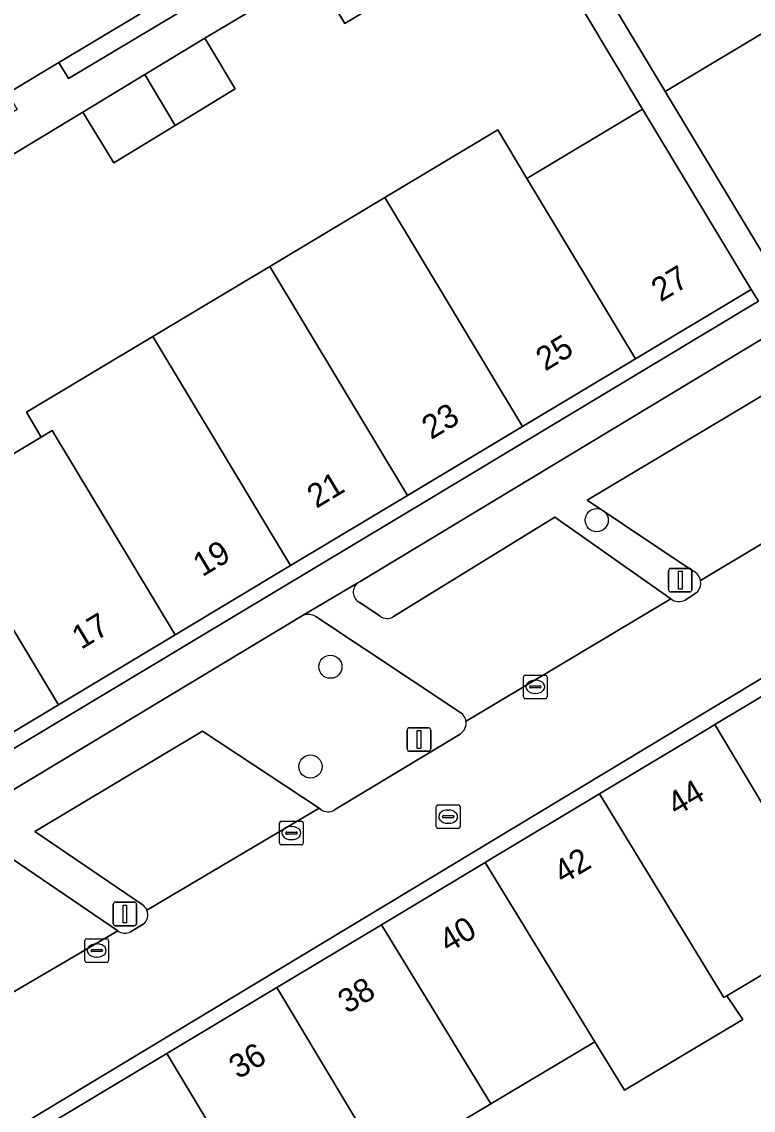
# Model space of a CAD drawing. Extents: x 161771 to 163125, y 382475 to 383179.
# Drawn here: x 162265.66 to 162296.6, y 382884.75 to 382930.82 of the extents above; entities that cross this region are included whole.
import ezdxf

# ---------------------------------------------------------------- set-up
doc = ezdxf.new("R2010")
doc.units = 0
for name, color, linetype in [('IMGEO_Boom', 7, 'Continuous'), ('IMGEO_Erf', 7, 'Continuous'), ('IMGEO_Groenvoorziening', 7, 'Continuous'), ('IMGEO_Kolk', 7, 'Continuous'), ('IMGEO_Lichtmast', 7, 'Continuous'), ('IMGEO_Pand', 7, 'Continuous'), ('IMGEO_Pand_nummerreeks', 7, 'Continuous'), ('IMGEO_Parkeervlak_open', 7, 'Continuous'), ('IMGEO_Rioolput', 7, 'Continuous'), ('IMGEO_Voetpad_open', 7, 'Continuous'), ('IMGEO_Woonerf_open', 7, 'Continuous')]:
    doc.layers.add(name, color=color, linetype=linetype)

msp = doc.modelspace()

# ---------------------------------------------------------------- linework, layer by layer
at = {"layer": 'IMGEO_Boom'}
for centre in [(162289.978, 382909.728), (162278.713, 382903.523), (162277.873, 382899.3)]:
    msp.add_circle(centre, 0.489, dxfattribs=at)
at = {"layer": 'IMGEO_Erf'}
for points in [[(162262.013, 382910.567), (162266.485, 382913.246), (162265.858, 382914.293), (162271.211, 382917.503), (162276.152, 382920.466), (162281.023, 382923.387), (162285.792, 382926.247), (162287.024, 382924.194), (162291.914, 382927.129), (162285.715, 382937.507)], [(162281.803, 382932.258), (162279.323, 382930.753), (162278.026, 382932.89), (162273.401, 382930.122), (162274.693, 382927.982), (162272.15, 382926.433), (162269.55, 382924.849), (162268.251, 382927.002), (162263.671, 382924.234)], [(162303.877, 382907.217), (162266.56, 382884.689), (162262.058, 382881.971), (162248.32, 382873.678), (162240.406, 382868.9), (162233.779, 382879.947)], [(162236.885, 382871.083), (162239.66, 382866.479), (162244.449, 382869.355), (162248.972, 382872.07), (162251.245, 382873.435), (162253.519, 382874.8), (162253.925, 382875.044), (162253.312, 382876.074), (162257.837, 382878.767), (162262.352, 382881.479), (162266.86, 382884.187), (162271.804, 382887.157), (162276.448, 382889.947), (162280.878, 382892.607), (162285.267, 382895.243), (162285.489, 382895.377), (162290.1, 382898.147), (162294.711, 382900.917), (162294.978, 382901.077), (162299.213, 382903.621)], [(162300.168, 382892.396), (162295.482, 382889.595), (162296.156, 382888.587), (162291.149, 382885.601), (162289.899, 382887.65), (162285.499, 382885.022), (162281.001, 382882.337), (162281.673, 382881.295), (162276.987, 382878.494), (162277.661, 382877.486), (162272.654, 382874.5), (162271.398, 382876.603), (162266.883, 382873.907), (162262.361, 382871.206), (162257.821, 382868.496), (162259.108, 382866.333), (162254.113, 382863.36), (162253.512, 382864.374), (162249.033, 382861.693), (162244.335, 382858.88), (162238.836, 382855.588)]]:
    msp.add_lwpolyline(points, dxfattribs=at)
msp.add_lwpolyline([(162296.82, 382918.994), (162296.509, 382919.492), (162291.612, 382916.553), (162286.844, 382913.691), (162281.974, 382910.768), (162277.034, 382907.803), (162272.149, 382904.871), (162267.212, 382901.908), (162261.895, 382898.717), (162262.21, 382898.195), (162282.281, 382910.257)], close=True, dxfattribs=at)
at = {"layer": 'IMGEO_Groenvoorziening'}
msp.add_lwpolyline([(162273.693, 382932.984), (162267.225, 382929.098), (162267.646, 382928.417), (162274.104, 382932.301)], close=True, dxfattribs=at)
for points in [[(162297.006, 382917.412), (162279.978, 382907.135), (162279.87, 382907.071)], [(162289.571, 382910.581), (162298.495, 382915.904)], [(162294.061, 382907.566), (162289.571, 382910.581)], [(162281.384, 382905.65), (162288.207, 382909.855), (162293.118, 382906.394)], [(162293.716, 382906.349), (162294.179, 382906.647)], [(162279.937, 382906.257), (162280.807, 382905.673)], [(162277.57, 382905.706), (162263.657, 382897.322), (162263.621, 382897.301)], [(162284.232, 382901.576), (162278.098, 382905.651)], [(162270.759, 382893.457), (162266.22, 382896.553), (162273.303, 382900.803), (162278.236, 382897.536), (162278.293, 382897.498)], [(162278.89, 382897.465), (162284.198, 382900.673)], [(162263.657, 382896.487), (162269.722, 382892.346)], [(162270.268, 382892.306), (162270.8, 382892.625)]]:
    msp.add_lwpolyline(points, dxfattribs=at)
for centre, radius, start, end in [((162293.836, 382907.072), 0.543, 10.3968, 65.5333), ((162280.171, 382906.686), 0.489, 128.052, 241.3588), ((162293.837, 382907.068), 0.542, 309.0544, 10.8212), ((162293.455, 382906.872), 0.585, 234.8516, 296.5415), ((162277.776, 382905.122), 0.619, 58.6595, 109.4468), ((162281.111, 382906.05), 0.484, 231.0902, 304.3444), ((162283.908, 382901.133), 0.549, 9.2422, 53.8647), ((162283.91, 382901.137), 0.546, 301.7922, 8.8167), ((162278.614, 382897.895), 0.511, 231.0026, 302.6696), ((162270.473, 382893.025), 0.518, 21.8831, 56.5389), ((162270.472, 382893.027), 0.519, 309.2397, 21.6444), ((162270.028, 382892.771), 0.524, 234.2974, 297.3226)]:
    msp.add_arc(centre, radius, start, end, dxfattribs=at)
at = {"layer": 'IMGEO_Kolk'}
for p, q in [((162286.881, 382902.247), (162286.881, 382903.099)), ((162286.956, 382903.173), (162287.808, 382903.173)), ((162287.369, 382902.953), (162287.394, 382902.953)), ((162287.882, 382903.099), (162287.882, 382902.247)), ((162287.14, 382902.667), (162287.14, 382902.679)), ((162287.578, 382902.63), (162287.18, 382902.63)), ((162287.183, 382902.716), (162287.581, 382902.716)), ((162287.392, 382902.393), (162287.367, 382902.393)), ((162287.624, 382902.679), (162287.624, 382902.667)), ((162287.808, 382902.173), (162286.956, 382902.173)), ((162276.565, 382896.059), (162276.565, 382896.911)), ((162276.64, 382896.985), (162277.492, 382896.985)), ((162277.053, 382896.765), (162277.078, 382896.765)), ((162277.566, 382896.911), (162277.566, 382896.059)), ((162276.824, 382896.479), (162276.824, 382896.491)), ((162277.262, 382896.442), (162276.864, 382896.442)), ((162276.867, 382896.528), (162277.265, 382896.528)), ((162277.308, 382896.491), (162277.308, 382896.479)), ((162277.492, 382895.985), (162276.64, 382895.985)), ((162277.076, 382896.205), (162277.051, 382896.205)), ((162268.335, 382891.087), (162268.335, 382891.939)), ((162268.41, 382892.013), (162269.262, 382892.013)), ((162268.823, 382891.793), (162268.848, 382891.793)), ((162269.336, 382891.939), (162269.336, 382891.087)), ((162268.594, 382891.507), (162268.594, 382891.519)), ((162269.032, 382891.47), (162268.634, 382891.47)), ((162268.637, 382891.556), (162269.035, 382891.556)), ((162268.846, 382891.233), (162268.821, 382891.233)), ((162269.078, 382891.519), (162269.078, 382891.507)), ((162269.262, 382891.013), (162268.41, 382891.013))]:
    msp.add_line(p, q, dxfattribs=at)
for points in [[(162286.881, 382902.247), (162286.881, 382903.099)], [(162286.956, 382903.173), (162287.808, 382903.173)], [(162287.882, 382903.099), (162287.882, 382902.247)], [(162287.808, 382902.173), (162286.956, 382902.173)], [(162276.565, 382896.059), (162276.565, 382896.911)], [(162276.64, 382896.985), (162277.492, 382896.985)], [(162277.566, 382896.911), (162277.566, 382896.059)], [(162277.492, 382895.985), (162276.64, 382895.985)], [(162268.335, 382891.087), (162268.335, 382891.939)], [(162268.41, 382892.013), (162269.262, 382892.013)], [(162269.336, 382891.939), (162269.336, 382891.087)], [(162269.262, 382891.013), (162268.41, 382891.013)]]:
    msp.add_lwpolyline(points, dxfattribs=at)
for centre, radius, start, end in [((162286.958, 382903.097), 0.0765, 91.552, 178.448), ((162286.958, 382903.097), 0.0765, 91.552, 178.448), ((162287.806, 382903.097), 0.0765, 1.552, 88.448), ((162287.806, 382903.097), 0.0765, 1.552, 88.448), ((162287.18, 382902.676), 0.0403, 85.8775, 175.7526), ((162287.177, 382902.666), 0.0366, 178.938, 274.7102), ((162287.581, 382902.673), 0.043, 264.8664, 352.4533), ((162287.585, 382902.678), 0.0386, 1.7309, 96.639), ((162286.958, 382902.249), 0.0765, 181.552, 268.448), ((162286.958, 382902.249), 0.0765, 181.552, 268.448), ((162287.806, 382902.249), 0.0765, 271.552, 358.448), ((162287.806, 382902.249), 0.0765, 271.552, 358.448), ((162276.642, 382896.909), 0.0765, 91.552, 178.448), ((162276.642, 382896.909), 0.0765, 91.552, 178.448), ((162277.49, 382896.909), 0.0765, 1.552, 88.448), ((162277.49, 382896.909), 0.0765, 1.552, 88.448), ((162276.864, 382896.488), 0.0403, 85.8775, 175.7526), ((162276.861, 382896.478), 0.0366, 178.938, 274.7102), ((162277.265, 382896.485), 0.043, 264.8664, 352.4533), ((162277.269, 382896.49), 0.0386, 1.7309, 96.639), ((162276.642, 382896.061), 0.0765, 181.552, 268.448), ((162276.642, 382896.061), 0.0765, 181.552, 268.448), ((162277.49, 382896.061), 0.0765, 271.552, 358.448), ((162277.49, 382896.061), 0.0765, 271.552, 358.448), ((162268.412, 382891.937), 0.0765, 91.552, 178.448), ((162268.412, 382891.937), 0.0765, 91.552, 178.448), ((162269.26, 382891.937), 0.0765, 1.552, 88.448), ((162269.26, 382891.937), 0.0765, 1.552, 88.448), ((162268.634, 382891.516), 0.0403, 85.8775, 175.7526), ((162268.631, 382891.506), 0.0366, 178.938, 274.7102), ((162269.035, 382891.513), 0.043, 264.8664, 352.4533), ((162269.039, 382891.518), 0.0386, 1.7309, 96.639), ((162268.412, 382891.089), 0.0765, 181.552, 268.448), ((162268.412, 382891.089), 0.0765, 181.552, 268.448), ((162269.26, 382891.089), 0.0765, 271.552, 358.448), ((162269.26, 382891.089), 0.0765, 271.552, 358.448)]:
    msp.add_arc(centre, radius, start, end, dxfattribs=at)
for centre, major_axis, ratio, start_param, end_param in [((162287.368, 382902.673), (-0.387, 0.002), 0.722429, 4.712389, 7.853982), ((162287.393, 382902.673), (-0.39, 0.002), 0.717154, 1.570796, 4.712389), ((162277.052, 382896.485), (-0.387, 0.002), 0.722429, 4.712389, 7.853982), ((162277.077, 382896.485), (-0.39, 0.002), 0.717154, 1.570796, 4.712389), ((162268.822, 382891.513), (-0.387, 0.002), 0.722429, 4.712389, 7.853982), ((162268.847, 382891.513), (-0.39, 0.002), 0.717154, 1.570796, 4.712389)]:
    msp.add_ellipse(centre, major_axis=major_axis, ratio=ratio, start_param=start_param, end_param=end_param, dxfattribs=at)
at = {"layer": 'IMGEO_Lichtmast'}
for p, q in [((162293.017, 382906.788), (162293.017, 382907.588)), ((162293.017, 382907.588), (162293.017, 382906.788)), ((162293.117, 382907.688), (162293.907, 382907.688)), ((162293.907, 382907.688), (162293.117, 382907.688)), ((162294.007, 382907.588), (162294.007, 382906.788)), ((162294.007, 382906.788), (162294.007, 382907.588)), ((162293.907, 382906.688), (162293.117, 382906.688)), ((162293.117, 382906.688), (162293.907, 382906.688)), ((162282.066, 382900.945), (162282.856, 382900.945)), ((162282.856, 382900.945), (162282.066, 382900.945)), ((162281.966, 382900.045), (162281.966, 382900.845)), ((162281.966, 382900.845), (162281.966, 382900.045)), ((162282.956, 382900.845), (162282.956, 382900.045)), ((162282.956, 382900.045), (162282.956, 382900.845)), ((162282.856, 382899.945), (162282.066, 382899.945)), ((162282.066, 382899.945), (162282.856, 382899.945)), ((162269.629, 382893.561), (162270.419, 382893.561)), ((162270.419, 382893.561), (162269.629, 382893.561)), ((162269.529, 382892.661), (162269.529, 382893.461)), ((162269.529, 382893.461), (162269.529, 382892.661)), ((162270.519, 382893.461), (162270.519, 382892.661)), ((162270.519, 382892.661), (162270.519, 382893.461)), ((162270.419, 382892.561), (162269.629, 382892.561)), ((162269.629, 382892.561), (162270.419, 382892.561))]:
    msp.add_line(p, q, dxfattribs=at)
for points in [[(162293.437, 382907.563), (162293.587, 382907.563), (162293.587, 382906.813), (162293.437, 382906.813), (162293.437, 382907.563)], [(162282.386, 382900.82), (162282.536, 382900.82), (162282.536, 382900.07), (162282.386, 382900.07), (162282.386, 382900.82)], [(162269.949, 382893.436), (162270.099, 382893.436), (162270.099, 382892.686), (162269.949, 382892.686), (162269.949, 382893.436)]]:
    msp.add_lwpolyline(points, dxfattribs=at)
for centre, start, end in [((162293.117, 382907.588), 90, 180), ((162293.117, 382907.588), 90, 180), ((162293.907, 382907.588), 0, 90), ((162293.907, 382907.588), 360, 90), ((162293.117, 382906.788), 180, 270), ((162293.117, 382906.788), 180, 270), ((162293.907, 382906.788), 270, 0), ((162293.907, 382906.788), 270, 0), ((162282.066, 382900.845), 90, 180), ((162282.066, 382900.845), 90, 180), ((162282.856, 382900.845), 0, 90), ((162282.856, 382900.845), 360, 90), ((162282.066, 382900.045), 180, 270), ((162282.066, 382900.045), 180, 270), ((162282.856, 382900.045), 270, 0), ((162282.856, 382900.045), 270, 0), ((162269.629, 382893.461), 90, 180), ((162269.629, 382893.461), 90, 180), ((162270.419, 382893.461), 0, 90), ((162270.419, 382893.461), 360, 90), ((162269.629, 382892.661), 180, 270), ((162269.629, 382892.661), 180, 270), ((162270.419, 382892.661), 270, 0), ((162270.419, 382892.661), 270, 0)]:
    msp.add_arc(centre, 0.1, start, end, dxfattribs=at)
at = {"layer": 'IMGEO_Pand'}
for points in [[(162297.285, 382934.252), (162297.688, 382934.494), (162297.611, 382934.622), (162297.208, 382934.381), (162296.18, 382936.096), (162296.583, 382936.338), (162296.506, 382936.467), (162296.103, 382936.225), (162295.07, 382937.949), (162295.473, 382938.191), (162294.367, 382940.032), (162287.906, 382936.148), (162292.878, 382927.875), (162299.33, 382931.753), (162298.716, 382932.778), (162298.313, 382932.537)], [(162280.521, 382934.404), (162278.026, 382932.89), (162279.323, 382930.753), (162281.803, 382932.258)], [(162302.89, 382925.813), (162302.487, 382925.571), (162301.459, 382927.287), (162301.862, 382927.528), (162301.785, 382927.657), (162301.382, 382927.416), (162300.354, 382929.131), (162300.757, 382929.373), (162300.68, 382929.501), (162300.277, 382929.26), (162299.249, 382930.975), (162299.652, 382931.217), (162299.33, 382931.753), (162292.878, 382927.875), (162297.851, 382919.602), (162304.231, 382923.465), (162304.281, 382923.496)], [(162273.401, 382930.122), (162270.864, 382928.585), (162272.15, 382926.433), (162274.693, 382927.982)], [(162270.864, 382928.585), (162268.251, 382927.002), (162269.55, 382924.849), (162272.15, 382926.433)], [(162291.914, 382927.129), (162287.024, 382924.194), (162291.612, 382916.553), (162296.509, 382919.492)], [(162287.024, 382924.194), (162285.792, 382926.247), (162281.023, 382923.387), (162286.844, 382913.691), (162291.612, 382916.553)], [(162281.023, 382923.387), (162276.152, 382920.466), (162281.974, 382910.768), (162286.844, 382913.691)], [(162276.152, 382920.466), (162271.211, 382917.503), (162277.034, 382907.803), (162281.974, 382910.768)], [(162271.211, 382917.503), (162265.858, 382914.293), (162266.485, 382913.246), (162266.953, 382913.526), (162272.149, 382904.871), (162277.034, 382907.803)], [(162266.953, 382913.526), (162266.485, 382913.246), (162262.013, 382910.567), (162267.212, 382901.908), (162272.149, 382904.871)], [(162262.013, 382910.567), (162256.693, 382907.381), (162261.895, 382898.717), (162267.212, 382901.908)], [(162299.213, 382903.621), (162294.978, 382901.077), (162299.56, 382893.413), (162303.819, 382895.981)], [(162294.978, 382901.077), (162294.711, 382900.917), (162290.1, 382898.147), (162295.356, 382889.521), (162295.482, 382889.595), (162300.168, 382892.396), (162299.56, 382893.413)], [(162290.1, 382898.147), (162285.489, 382895.377), (162285.267, 382895.243), (162289.899, 382887.65), (162291.149, 382885.601), (162296.156, 382888.587), (162295.482, 382889.595), (162295.356, 382889.521)], [(162285.267, 382895.243), (162280.878, 382892.607), (162285.499, 382885.022), (162289.899, 382887.65)], [(162280.878, 382892.607), (162276.448, 382889.947), (162281.001, 382882.337), (162285.499, 382885.022)], [(162276.448, 382889.947), (162271.804, 382887.157), (162276.349, 382879.559), (162276.987, 382878.494), (162281.673, 382881.295), (162281.001, 382882.337)], [(162271.804, 382887.157), (162266.86, 382884.187), (162271.398, 382876.603), (162272.654, 382874.5), (162277.661, 382877.486), (162276.987, 382878.494), (162276.349, 382879.559)]]:
    msp.add_lwpolyline(points, close=True, dxfattribs=at)
at = {"layer": 'IMGEO_Parkeervlak_open'}
msp.add_lwpolyline([(162273.693, 382932.984), (162275.837, 382934.287), (162284.521, 382939.511), (162284.226, 382940.002), (162284.206, 382939.99), (162281.948, 382938.622), (162279.655, 382942.407), (162279.62, 382942.465), (162247.373, 382923.049), (162249.976, 382918.709), (162256.442, 382922.595), (162258.6, 382923.904), (162265.073, 382927.797), (162267.225, 382929.098)], close=True, dxfattribs=at)
for points in [[(162298.495, 382915.904), (162289.571, 382910.581), (162294.061, 382907.566)], [(162294.37, 382907.17), (162305.473, 382913.83)], [(162293.118, 382906.394), (162288.207, 382909.855), (162281.384, 382905.65)], [(162279.87, 382907.071), (162277.57, 382905.706)], [(162280.807, 382905.673), (162279.937, 382906.257)], [(162284.45, 382901.221), (162293.118, 382906.394)], [(162278.098, 382905.651), (162284.232, 382901.576)], [(162278.236, 382897.536), (162273.303, 382900.803), (162266.22, 382896.553), (162270.759, 382893.457)], [(162270.954, 382893.218), (162278.236, 382897.536)], [(162258.721, 382885.902), (162269.722, 382892.346), (162263.657, 382896.487)]]:
    msp.add_lwpolyline(points, dxfattribs=at)
for centre, radius, start, end in [((162293.836, 382907.072), 0.543, 10.3968, 65.5333), ((162280.171, 382906.686), 0.489, 128.052, 241.3588), ((162277.776, 382905.122), 0.619, 58.6595, 109.4468), ((162281.111, 382906.05), 0.484, 231.0902, 304.3444), ((162283.908, 382901.133), 0.549, 9.2422, 53.8647), ((162270.473, 382893.025), 0.518, 21.8831, 56.5389)]:
    msp.add_arc(centre, radius, start, end, dxfattribs=at)
at = {"layer": 'IMGEO_Rioolput'}
for p, q in [((162283.195, 382896.753), (162283.195, 382897.605)), ((162283.27, 382897.679), (162284.122, 382897.679)), ((162283.497, 382897.222), (162283.895, 382897.222)), ((162283.683, 382897.459), (162283.708, 382897.459)), ((162284.196, 382897.605), (162284.196, 382896.753)), ((162283.454, 382897.173), (162283.454, 382897.185)), ((162283.892, 382897.136), (162283.494, 382897.136)), ((162283.706, 382896.899), (162283.681, 382896.899)), ((162283.938, 382897.185), (162283.938, 382897.173)), ((162284.122, 382896.679), (162283.27, 382896.679))]:
    msp.add_line(p, q, dxfattribs=at)
for points in [[(162283.195, 382896.753), (162283.195, 382897.605)], [(162283.27, 382897.679), (162284.122, 382897.679)], [(162284.196, 382897.605), (162284.196, 382896.753)], [(162284.122, 382896.679), (162283.27, 382896.679)]]:
    msp.add_lwpolyline(points, dxfattribs=at)
for centre, radius, start, end in [((162283.272, 382897.603), 0.0765, 91.552, 178.448), ((162283.272, 382897.603), 0.0765, 91.552, 178.448), ((162283.494, 382897.182), 0.0403, 85.8775, 175.7526), ((162283.899, 382897.184), 0.0386, 1.7309, 96.639), ((162284.12, 382897.603), 0.0765, 1.552, 88.448), ((162284.12, 382897.603), 0.0765, 1.552, 88.448), ((162283.491, 382897.172), 0.0366, 178.938, 274.7102), ((162283.895, 382897.179), 0.043, 264.8664, 352.4533), ((162283.272, 382896.755), 0.0765, 181.552, 268.448), ((162283.272, 382896.755), 0.0765, 181.552, 268.448), ((162284.12, 382896.755), 0.0765, 271.552, 358.448), ((162284.12, 382896.755), 0.0765, 271.552, 358.448)]:
    msp.add_arc(centre, radius, start, end, dxfattribs=at)
for centre, major_axis, ratio, start_param, end_param in [((162283.682, 382897.179), (-0.387, 0.002), 0.722429, 4.712389, 7.853982), ((162283.707, 382897.179), (-0.39, 0.002), 0.717154, 1.570796, 4.712389)]:
    msp.add_ellipse(centre, major_axis=major_axis, ratio=ratio, start_param=start_param, end_param=end_param, dxfattribs=at)
at = {"layer": 'IMGEO_Voetpad_open'}
for points in [[(162297.851, 382919.602), (162292.878, 382927.875), (162287.906, 382936.148), (162282.933, 382944.421), (162289.399, 382948.285), (162289.52, 382948.357), (162288.897, 382949.412), (162282.64, 382945.629), (162281.993, 382945.24)], [(162285.715, 382937.507), (162291.914, 382927.129), (162296.509, 382919.492), (162296.82, 382918.994)], [(162263.671, 382924.234), (162268.251, 382927.002), (162270.864, 382928.585), (162273.401, 382930.122), (162278.026, 382932.89)], [(162274.104, 382932.301), (162267.646, 382928.417), (162267.225, 382929.098), (162265.073, 382927.797), (162265.47, 382927.114), (162259.005, 382923.228), (162258.6, 382923.904), (162256.442, 382922.595), (162256.862, 382921.911), (162250.378, 382918.025), (162249.976, 382918.709), (162247.373, 382923.049), (162244.225, 382928.275), (162241.633, 382932.605)], [(162296.82, 382918.994), (162282.281, 382910.257), (162262.21, 382898.195), (162261.002, 382897.457), (162257.574, 382895.517), (162257.637, 382895.444), (162252.867, 382892.667), (162252.905, 382892.614), (162250.934, 382891.427), (162245.074, 382887.826), (162246.469, 382886.872), (162251.847, 382890.276), (162254.231, 382891.654), (162261.271, 382895.911), (162261.405, 382895.99), (162263.621, 382897.301), (162263.657, 382897.322), (162277.57, 382905.706), (162279.87, 382907.071), (162279.978, 382907.135), (162297.006, 382917.412)]]:
    msp.add_lwpolyline(points, dxfattribs=at)
at = {"layer": 'IMGEO_Woonerf_open'}
for points in [[(162305.473, 382913.83), (162294.37, 382907.17)], [(162246.123, 382877.332), (162247.25, 382875.451), (162248.32, 382873.678), (162262.058, 382881.971), (162266.56, 382884.689), (162303.877, 382907.217)], [(162294.179, 382906.647), (162293.716, 382906.349)], [(162293.118, 382906.394), (162284.45, 382901.221)], [(162284.198, 382900.673), (162278.89, 382897.465)], [(162278.293, 382897.498), (162278.236, 382897.536), (162270.954, 382893.218)], [(162270.8, 382892.625), (162270.268, 382892.306)], [(162269.722, 382892.346), (162258.721, 382885.902)]]:
    msp.add_lwpolyline(points, dxfattribs=at)
for centre, radius, start, end in [((162293.837, 382907.068), 0.542, 309.0544, 10.8212), ((162293.455, 382906.872), 0.585, 234.8516, 296.5415), ((162283.91, 382901.137), 0.546, 301.7922, 8.8167), ((162278.614, 382897.895), 0.511, 231.0026, 302.6696), ((162270.472, 382893.027), 0.519, 309.2397, 21.6444), ((162270.028, 382892.771), 0.524, 234.2974, 297.3226)]:
    msp.add_arc(centre, radius, start, end, dxfattribs=at)

# ---------------------------------------------------------------- texts
at = {"layer": 'IMGEO_Pand_nummerreeks'}
for s, rotation, p in [('27', 30.9722, (162292.677, 382918.941)), ('25', 30.9722, (162287.798, 382916.013)), ('23', 30.9722, (162282.974, 382913.118)), ('21', 30.9722, (162278.122, 382910.206)), ('19', 30.9722, (162273.298, 382907.31)), ('17', 30.9722, (162268.174, 382904.235)), ('44', 30.9913, (162293.351, 382897.184)), ('42', 30.9913, (162288.549, 382894.299)), ('40', 30.9913, (162283.703, 382891.388)), ('38', 30.9913, (162279.424, 382888.818)), ('36', 30.9935, (162274.814, 382886.048))]:
    msp.add_text(s, height=1, rotation=rotation, dxfattribs=at).set_placement(p)

doc.saveas('drawing.dxf')
